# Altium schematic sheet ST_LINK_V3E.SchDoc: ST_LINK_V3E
size A3; Date: Not used; ApprovedBy: Not used; CheckedBy: Not used; Author: Not used; CompanyName: STMicroelectronics; DrawnBy: Not used; Engineer: Not used; Organization: Not used; Address1: Not used; Address2: Not used; Address3: Not used; Address4: Not used; DocumentNumber: Not used; Revision: Not used; SheetNumber: 15; SheetTotal: 16
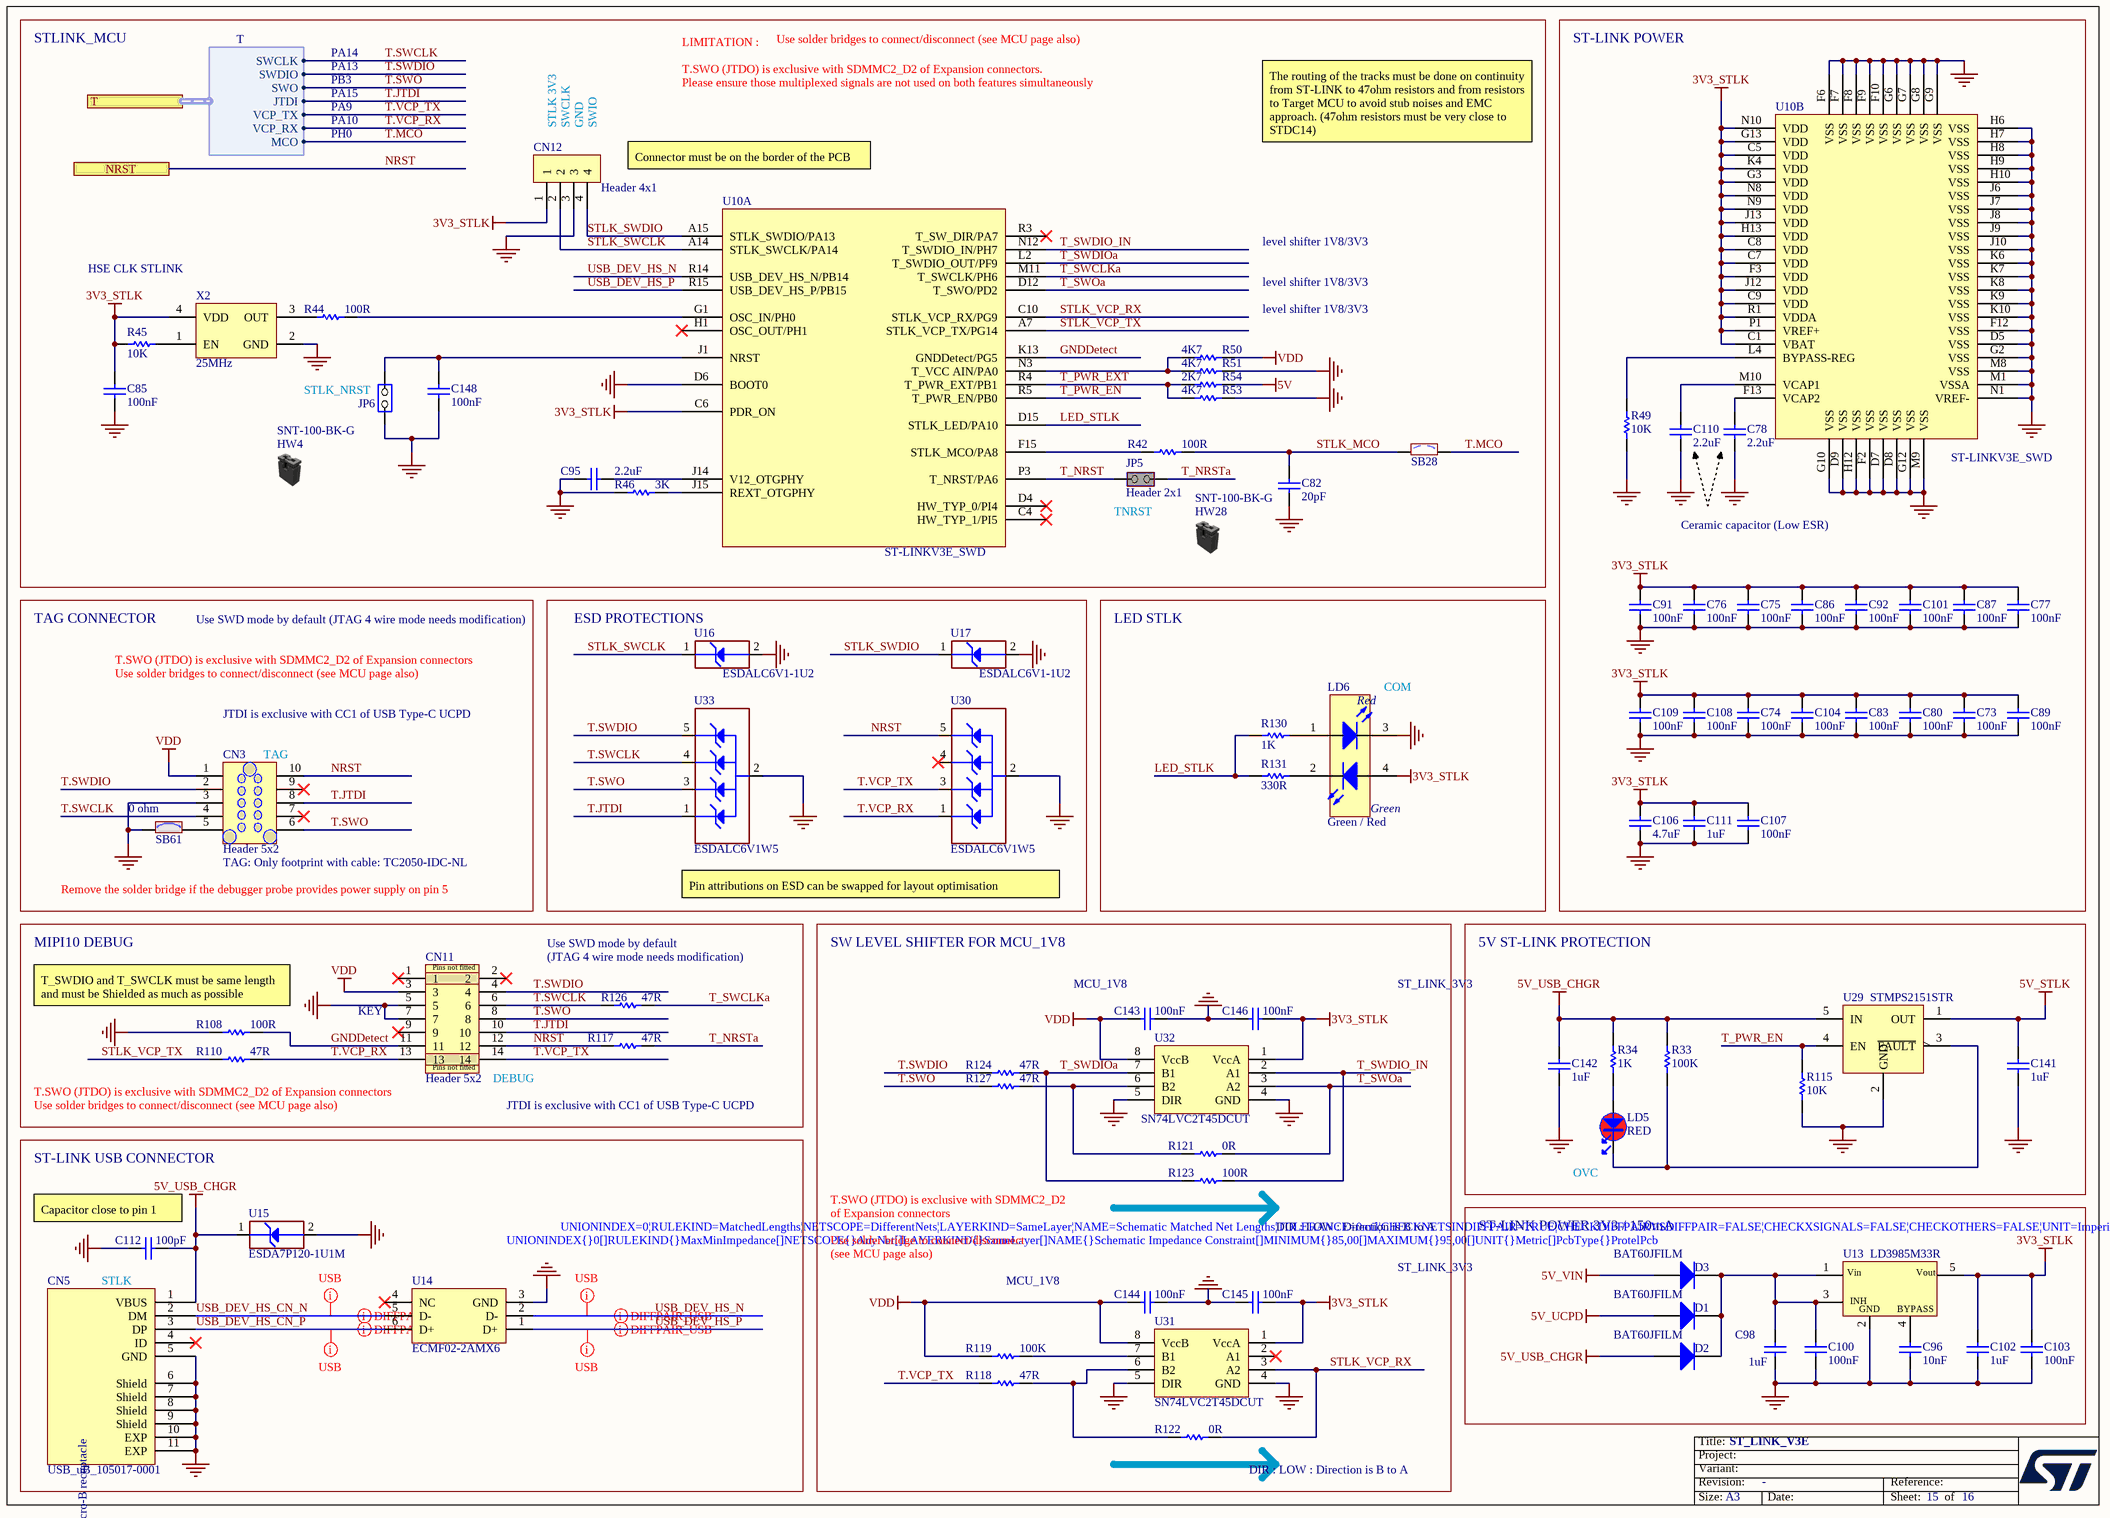
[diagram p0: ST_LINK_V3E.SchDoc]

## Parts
C73  value 100nF  [C0402]  (hidden comment: Capacitor)
C74  value 100nF  [C0402]  (hidden comment: Capacitor)
C75  value 100nF  [C0402]  (hidden comment: Capacitor)
C76  value 100nF  [C0402]  (hidden comment: Capacitor)
C77  value 100nF  [C0402]  (hidden comment: Capacitor)
C78  value 2.2uF  [C0603]  (hidden comment: Capacitor)
C80  value 100nF  [C0402]  (hidden comment: Capacitor)
C82  value 20pF  [C0402]  (hidden comment: Capacitor)
C83  value 100nF  [C0402]  (hidden comment: Capacitor)
C85  value 100nF  [C0402]  (hidden comment: Capacitor)
C86  value 100nF  [C0402]  (hidden comment: Capacitor)
C87  value 100nF  [C0402]  (hidden comment: Capacitor)
C89  value 100nF  [C0402]  (hidden comment: Capacitor)
C91  value 100nF  [C0402]  (hidden comment: Capacitor)
C92  value 100nF  [C0402]  (hidden comment: Capacitor)
C95  value 2.2uF  [C0603]  (hidden comment: Capacitor)
C96  value 10nF  [C0402]  (hidden comment: Capacitor)
C98  value 1uF  [C0402]  (hidden comment: Capacitor)
C100  value 100nF  [C0402]  (hidden comment: Capacitor)
C101  value 100nF  [C0402]  (hidden comment: Capacitor)
C102  value 1uF  [C0402]  (hidden comment: Capacitor)
C103  value 100nF  [C0402]  (hidden comment: Capacitor)
C104  value 100nF  [C0402]  (hidden comment: Capacitor)
C106  value 4.7uF  [C0603]  (hidden comment: Capacitor)
C107  value 100nF  [C0402]  (hidden comment: Capacitor)
C108  value 100nF  [C0402]  (hidden comment: Capacitor)
C109  value 100nF  [C0402]  (hidden comment: Capacitor)
C110  value 2.2uF  [C0603]  (hidden comment: Capacitor)
C111  value 1uF  [C0402]  (hidden comment: Capacitor)
C112  value 100pF  [C0402]  (hidden comment: Capacitor)
C141  value 1uF  [C0402]  (hidden comment: Capacitor)
C142  value 1uF  [C0402]  (hidden comment: Capacitor)
C143  value 100nF  [C0402]  (hidden comment: Capacitor)
C144  value 100nF  [C0402]  (hidden comment: Capacitor)
C145  value 100nF  [C0402]  (hidden comment: Capacitor)
C146  value 100nF  [C0402]  (hidden comment: Capacitor)
C148  value 100nF  [C0402]  (hidden comment: Capacitor)
CN3  value Header 5x2  [CON_TAG-C_TC2050-IDC-NL]  (hidden comment: Tag-10-C)
CN5  value USB_uB_105017-0001  [CON_USBMICROB_MOLEX_105017-0001_H2P90]  (hidden comment: USB_uB_105017.0001)
CN11  value Header 5x2  [CON_STDC14_Receiver_MEDIUM__3D_FTSH-105-01-L-DV-K]  (hidden comment: Header 7x2_MIPI10_on_STDC14)
CN12  Header 4x1  [CON_SAMTEC_TSW-104-07-G-S]
D1  BAT60JFILM  [DIO_SOD323]
D2  BAT60JFILM  [DIO_SOD323]
D3  BAT60JFILM  [DIO_SOD323]
HW4  value SNT-100-BK-G  (hidden comment: Shunt Black 2.54mm)  (mechanical)
HW28  value SNT-100-BK-G  (hidden comment: Shunt Black 2.54mm)  (mechanical)
JP5  value Header 2x1  [CON_SAMTEC_TSW-102-07-G-S]  (hidden comment: Jumper_Header 2x1 Fitted)
JP6  Jumper_Header 2x1  [CON_SAMTEC_TSW-102-07-G-S]  (value not drawn)
LD5  value RED  [LED_0603_OSRAM_LS-Q976-NR-1_RED_1A2K_H0P8]  (hidden comment: LED_red)
LD6  value Green / Red  [LED_BI-GR_WE-150141SV73110]  (hidden comment: LED_BICOLOR)
R33  value 100K  [R0402]  (hidden comment: Resistor)
R34  value 1K  [R0402]  (hidden comment: Resistor)
R42  value 100R  [R0402]  (hidden comment: Resistor)
R44  value 100R  [R0402]  (hidden comment: Resistor)
R45  value 10K  [R0402]  (hidden comment: Resistor)
R46  value 3K  [R0402]  (hidden comment: Resistor)
R49  value 10K  [R0402]  (hidden comment: Resistor)
R50  value 4K7  [R0402]  (hidden comment: Resistor)
R51  value 4K7  [R0402]  (hidden comment: Resistor)
R53  value 4K7  [R0402]  (hidden comment: Resistor)
R54  value 2K7  [R0402]  (hidden comment: Resistor)
R108  value 100R  [R0402]  (hidden comment: Resistor)
R110  value 47R  [R0402]  (hidden comment: Resistor)
R115  value 10K  [R0402]  (hidden comment: Resistor)
R117  value 47R  [R0402]  (hidden comment: Resistor)
R118  value 47R  [R0402]  (hidden comment: Resistor)
R119  value 100K  [R0402]  (hidden comment: Resistor)
R121  value 0R  [R0402]  (hidden comment: Resistor)
R122  value 0R  [R0402]  (hidden comment: Resistor)
R123  value 100R  [R0402]  (hidden comment: Resistor)
R124  value 47R  [R0402]  (hidden comment: Resistor)
R126  value 47R  [R0402]  (hidden comment: Resistor)
R127  value 47R  [R0402]  (hidden comment: Resistor)
R130  value 1K  [R0402]  (hidden comment: Resistor)
R131  value 330R  [R0402]  (hidden comment: Resistor)
SB28  SB_OFF  [SOLDER-BRIDGE_R0402-0R]  (value not drawn)
SB61  value 0 ohm  [SOLDER-BRIDGE_R0402-0R]  (hidden comment: SB_ON)
U10  ST-LINKV3E_SWD  [ICC_UFBGA201_176+25_10X10_P065]  (parts A,B of 2)
U13  LD3985M33R  [REG_SOT23-5L]
U14  ECMF02-2AMX6  [ESD_QFN-6L_1P7X1P5_P050]
U15  value ESDA7P120-1U1M  [ESD_QFN1610_2N_1K_2A]  (hidden comment: ESD-TRANSIL)
U16  value ESDALC6V1-1U2  [ESD_ST0201]  (hidden comment: ESD-TRANSIL)
U17  value ESDALC6V1-1U2  [ESD_ST0201]  (hidden comment: ESD-TRANSIL)
U29  STMPS2151STR  [MOS_SOT23-5L]
U30  ESDALC6V1W5  [ESD_SOT323-5L]
U31  SN74LVC2T45DCUT  [ICC_VSSOP8_DCU_R-PDSO-G8_2X2P30_P050]
U32  SN74LVC2T45DCUT  [ICC_VSSOP8_DCU_R-PDSO-G8_2X2P30_P050]
U33  ESDALC6V1W5  [ESD_SOT323-5L]
X2  value 25MHz  [OSC_NDK_NZ2520SB_4P]  (hidden comment: OSCILLATOR_4_PINS)

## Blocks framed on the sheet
STLINK_MCU: C82 C85 C95 C148 CN12 HW4 HW28 JP5 JP6 R42 R44-R46 R50 R51 R53 R54 SB28 U10 X2
ST-LINK POWER: C73-C78 C80 C83 C86 C87 C89 C91 C92 C101 C104 C106-C111 R49 U10
TAG CONNECTOR: CN3 SB61
ESD PROTECTIONS: U16 U17 U30 U33
LED STLK: LD6 R130 R131
MIPI10 DEBUG: CN11 R108 R110 R117 R126
SW LEVEL SHIFTER FOR MCU_1V8: C143-C146 R118 R119 R121-R124 R127 U31 U32
5V ST-LINK PROTECTION: C141 C142 LD5 R33 R34 R115 U29
ST-LINK USB CONNECTOR: C112 CN5 U14 U15
ST-LINK POWER 3V3 / 150mA: C96 C98 C100 C102 C103 D1-D3 U13

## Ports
NRST, T (harness T)

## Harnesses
T: SWCLK, SWDIO, SWO, JTDI, VCP_RX, VCP_TX, MCO

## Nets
3V3_STLK: C73.1 C74.1 C75.1 C76.1 C77.1 C80.1 C83.1 C85.1 C86.1 C87.1 C89.1 C91.1 C92.1 C101.1 C102.2 C103.2 C104.1 C106.2 C107.1 C108.1 C109.1 C111.2 C145.2 C146.2 CN12.1 LD6.4(Green_anode) R45.1 U10.C1(VBAT) U10.C5(VDD) U10.C6(PDR_ON) U10.C7(VDD) U10.C8(VDD) U10.C9(VDD) U10.F3(VDD) U10.G3(VDD) U10.G13(VDD) U10.H13(VDD) U10.J12(VDD) U10.J13(VDD) U10.K4(VDD) U10.N8(VDD) U10.N9(VDD) U10.N10(VDD) U10.P1(VREF+) U10.R1(VDDA) U13.5(Vout) U31.1(VccA) U32.1(VccA) X2.4(VDD)
5V: R54.1
5V_STLK: C141.2 U29.1(OUT)
5V_UCPD: D1.1(A)
5V_USB_CHGR: C112.2 C142.2 CN5.1(VBUS) D2.1(A) R33.2 R34.2 U15.1(IO1) U29.5(IN)
5V_VIN: D3.1(A)
GND: C73.2 C74.2 C75.2 C76.2 C77.2 C78.1 C80.2 C82.1 C83.2 C85.2 C86.2 C87.2 C89.2 C91.2 C92.2 C95.1 C96.1 C98.1 C100.1 C101.2 C102.1 C103.1 C104.2 C106.1 C107.2 C108.2 C109.2 C110.1 C111.1 C112.1 C141.1 C142.1 C143.2 C144.2 C145.1 C146.1 C148.2 CN3.3 CN5.5(GND) CN5.6(Shield) CN5.7(Shield) CN5.8(Shield) CN5.9(Shield) CN5.10(EXP) CN5.11(EXP) CN11.5 CN11.7 CN12.3 JP6.1(COMMON) LD6.3(RED_cathode) R46.1 R49.1 R51.2 R53.1 R108.1 R115.1 SB61.1 U10.D5(VSS) U10.D6(BOOT0) U10.D7(VSS) U10.D8(VSS) U10.D9(VSS) U10.F2(VSS) U10.F6(VSS) U10.F7(VSS) U10.F8(VSS) U10.F9(VSS) U10.F10(VSS) U10.F12(VSS) U10.G2(VSS) U10.G6(VSS) U10.G7(VSS) U10.G8(VSS) U10.G9(VSS) U10.G10(VSS) U10.G12(VSS) U10.H6(VSS) U10.H7(VSS) U10.H8(VSS) U10.H9(VSS) U10.H10(VSS) U10.H12(VSS) U10.J6(VSS) U10.J7(VSS) U10.J8(VSS) U10.J9(VSS) U10.J10(VSS) U10.K6(VSS) U10.K7(VSS) U10.K8(VSS) U10.K9(VSS) U10.K10(VSS) U10.M1(VSSA) U10.M8(VSS) U10.M9(VSS) U10.N1(VREF-) U13.2(GND) U14.3(GND) U15.2(GND) U16.2(GND) U17.2(GND) U29.2(GND) U30.2(GND) U31.4(GND) U31.5(DIR) U32.4(GND) U32.5(DIR) U33.2(GND) X2.2(GND)
VDD: C143.1 C144.1 CN3.1 CN11.3 R50.2 R119.1 U31.8(VccB) U32.8(VccB)
GNDDetect: CN11.11 R108.2 U10.K13(GNDDetect/PG5)
LED_STLK: R130.2 R131.2 U10.D15(STLK_LED/PA10)
NRST: CN3.10 CN11.12 R117.1 U30.5(IO4) ; port NRST
STLK_MCO: C82.2 R42.2 SB28.1
STLK_SWCLK: CN12.2 U10.A14(STLK_SWCLK/PA14) U16.1(IO1)
STLK_SWDIO: CN12.4 U10.A15(STLK_SWDIO/PA13) U17.1(IO1)
STLK_VCP_RX: R122.2 U10.C10(STLK_VCP_RX/PG9) U31.3(A2)
STLK_VCP_TX: R110.1 U10.A7(STLK_VCP_TX/PG14)
T.JTDI: CN3.8 CN11.10 U33.1(IO1) ; port T.JTDI
T.MCO: SB28.2 ; port T.MCO
T.SWCLK: CN3.4 CN11.6 R126.1 U33.4(IO3) ; port T.SWCLK
T.SWDIO: CN3.2 CN11.4 R124.1 U33.5(IO4) ; port T.SWDIO
T.SWO: CN3.6 CN11.8 R127.1 U33.3(IO2) ; port T.SWO
T.VCP_RX: CN11.13 R110.2 U30.1(IO1) ; port T.VCP_RX
T.VCP_TX: CN11.14 R118.1 U30.3(IO2) ; port T.VCP_TX
T_NRST: JP5.1(COMMON) U10.P3(T_NRST/PA6)
T_NRSTa: JP5.2(NO) R117.2
T_PWR_EN: R115.2 U10.R5(T_PWR_EN/PB0) U29.4(EN)
T_PWR_EXT: R53.2 R54.2 U10.R4(T_PWR_EXT/PB1)
T_SWCLKa: R126.2 U10.M11(T_SWCLK/PH6)
T_SWDIO_IN: R123.2 U10.N12(T_SWDIO_IN/PH7) U32.2(A1)
T_SWDIOa: R123.1 R124.2 U10.L2(T_SWDIO_OUT/PF9) U32.7(B1)
T_SWOa: R121.2 U10.D12(T_SWO/PD2) U32.3(A2)
USB_DEV_HS_CN_N: CN5.2(DM) U14.5(D-)
USB_DEV_HS_CN_P: CN5.3(DP) U14.6(D+)
USB_DEV_HS_N: U10.R14(USB_DEV_HS_N/PB14) U14.2(D-)
USB_DEV_HS_P: U10.R15(USB_DEV_HS_P/PB15) U14.1(D+)
NetC78_2: C78.2 U10.F13(VCAP2)
NetC95_2: C95.2 U10.J14(V12_OTGPHY)
NetC96_2: C96.2 U13.4(BYPASS)
NetC98_2: C98.2 C100.2 D1.2(K) D2.2(K) D3.2(K) U13.1(Vin) U13.3(CE)
NetC110_2: C110.2 U10.M10(VCAP1)
NetC148_1: C148.1 JP6.2(NO) U10.J1(NRST)
NetCN3_5: CN3.5 SB61.2
NetLD5_1: LD5.1 R34.1
NetLD5_2: LD5.2 R33.1 U29.3(~{FAULT})
NetLD6_1: LD6.1(Red_anode) R130.1
NetLD6_2: LD6.2(Green_cathode) R131.1
NetR42_1: R42.1 U10.F15(STLK_MCO/PA8)
NetR44_1: R44.1 X2.3(OUT)
NetR44_2: R44.2 U10.G1(OSC_IN/PH0)
NetR45_2: R45.2 X2.1(EN)
NetR46_2: R46.2 U10.J15(REXT_OTGPHY)
NetR49_2: R49.2 U10.L4(BYPASS-REG)
NetR50_1: R50.1 R51.1 U10.N3(T_VCC_AIN/PA0)
NetR118_2: R118.2 R122.1 U31.6(B2)
NetR119_2: R119.2 U31.7(B1)
NetR121_1: R121.1 R127.2 U32.6(B2)

Not connected (* = marked no-connect by the designer): CN3 7* 9*; CN5 4(ID)*; CN11 1* 2* 9*; U10 C4(HW_TYP_1/PI5)* D4(HW_TYP_0/PI4)* H1(OSC_OUT/PH1)* R3(T_SW_DIR/PA7)*; U14 4(NC)*; U30 4(IO3)*; U31 2(A1)*

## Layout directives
differential pair; rule Impedance Constraint [Min = 85.00    Max = 95.00    ]: USB_DEV_HS_CN_N, USB_DEV_HS_CN_P, USB_DEV_HS_N, USB_DEV_HS_P
rule Undefined; rule Matched Net Lengths [Tolerance = 0mil]; rule Impedance Constraint [Min = 85.00    Max = 95.00    ]: USB_DEV_HS_CN_N, USB_DEV_HS_CN_P, USB_DEV_HS_N, USB_DEV_HS_P

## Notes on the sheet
- Use solder bridges to connect/disconnect (see MCU page also)
- PA14
- PA13
- PB3
- PA15
- PA9
- LIMITATION :
  T.SWO (JTDO) is exclusive with SDMMC2_D2 of Expansion connectors.
  Please ensure those multiplexed signals are not used on both features simultaneously
- PA10
- PH0
- STLK 3V3
- SWCLK
- GND
- SWIO
- Connector must be on the border of the PCB
- The routing of the tracks must be done on continuity from ST-LINK to 47ohm resistors and from resistors to Target MCU to avoid stub noises and EMC approach. (47ohm resistors must be very close to STDC14)
- level shifter 1V8/3V3
- HSE CLK STLINK
- (near JP6) STLK_NRST
- (near JP5) TNRST
- Ceramic capacitor (Low ESR)
- Use SWD mode by default (JTAG 4 wire mode needs modification)
- T.SWO (JTDO) is exclusive with SDMMC2_D2 of Expansion connectors
- JTDI is exclusive with CC1 of USB Type-C UCPD
- (near LD6) COM
- (near CN3) TAG
- Remove the solder bridge if the debugger probe provides power supply on pin 5
- (near CN3) TAG: Only footprint with cable: TC2050-IDC-NL
- Pin attributions on ESD can be swapped for layout optimisation
- Use SWD mode by default
- (near R126) (JTAG 4 wire mode needs modification)
- MCU_1V8
- ST_LINK_3V3
- (near R108) T_SWDIO and T_SWCLK must be same length and must be Shielded as much as possible
- (near CN11) KEY
- (near CN11) DEBUG
- (near LD5) OVC
- (near C112) Capacitor close to pin 1
- T.SWO (JTDO) is exclusive with SDMMC2_D2
- of Expansion connectors
- Use solder bridge to connect/disconnect
- (see MCU page also)
- (near R123) DIR : LOW : Direction is B to A
- STLK
- (near R122) DIR : LOW : Direction is B to A

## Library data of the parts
C73-C77 C80 C83 C85-C87 C89 C91 C92 C100 C101 C103 C104 C107-C109 C143-C146 C148 = MCD-00006: Capacitor, MLCC, 100nF, 16V, X7R, +/-10%, 0402, T=0.5mm; Manufacturer_Part_Number: CC0402KRX7R7BB104; Manufacturer: YAGEO; Part_Preference: Recommended; Order_Code_RS: 616-9701; Component_Country_Of_Origin: China
C78 C95 C110 = MCD-00012: Capacitor, MLCC, 2.2uF, 10V, X5R, +/- 10%, 0603, T=0.8mm; Manufacturer_Part_Number: CC0603KRX5R6BB225; Manufacturer: YAGEO; BMS_Part_Number: 9142010; Part_Preference: Recommended; Component_Country_Of_Origin: China
C82 = MCD-00016: Capacitor, MLCC, 20pF, 50V, NPO, +/- 5%, 0402, T=0.5mm; Manufacturer_Part_Number: CC0402JRNPO9BN200; Manufacturer: YAGEO; Part_Preference: Recommended; Component_Country_Of_Origin: China
C96 = MCD-00011: Capacitor, MLCC, 10nF, 16V, X7R, +/-10%, 0402, T=0.5mm; Manufacturer_Part_Number: CC0402KRX7R7BB103; Manufacturer: YAGEO; Part_Preference: Recommended; Order_Code_RS: 669-8688; Component_Country_Of_Origin: China
C98 C102 C111 C141 C142 = MCD-02609: Capacitor, MLCC, 1uF, 25V, X5R, +/-10%, 0402, T=0.5mm; Part_Preference: Recommended; Manufacturer: YAGEO; Manufacturer_Part_Number: CC0402KRX5R8BB105
C106 = MCD-00009: Capacitor, MLCC, 4.7uF, 16V, X5R, +/-10%, 0603, T=0.8mm; Manufacturer_Part_Number: CC0603KRX5R7BB475; Manufacturer: YAGEO; Part_Preference: Recommended; Component_Country_Of_Origin: China
C112 = MCD-00205: Capacitor, MLCC, 100pF, 50V, NPO, +/-5%, 0402, T=0.5mm; Manufacturer_Part_Number: CC0402JRNPO9BN101; Manufacturer: YAGEO; Part_Preference: Recommended; Component_Country_Of_Origin: China
CN3 = MCD-00031: Header_Plug-of-nails, 5x2, 1.27mm, No legs; Part_Type: Connector; Manufacturer_Part_Number: TC2050-IDC-NL-FP; Manufacturer: TAG-CONNECTLLC; Part_Preference: Recommended
CN5 = MCD-00028: MicroUSB_TypeB, 5pins, 0.65mm, RA, SMD, T=2.9mm; Manufacturer_Part_Number: 1050170001; Manufacturer: MOLEX; Part_Type: Connector; Part_Preference: Recommended; Order_Code_RS: 848-6764; Component_Country_Of_Origin: Unknown
CN11 = MCD-02021: Header_MIPI10, 5x2, 1.27mm, VR, SMD, T=6.1mm; Part_Type: Connector; Manufacturer: SAMTEC; Manufacturer_Part_Number: FTSH-105-01-L-DV-K-P-TR; Part_Preference: Recommended; Component_Country_Of_Origin: China, Costa Rica, Malaysia, United States, Vietnam
CN12 = MCD-00029: Header, 4x1, 2.54mm, VR, TH, T=5.84mm/2.54mm; Manufacturer_Part_Number: TSW-104-07-G-S; Manufacturer: SAMTEC; Part_Type: Connector; Part_Preference: Recommended; Order_Code_RS: 161-2261; Component_Country_Of_Origin: China, Costa Rica, Malaysia, United States, Vietnam
D1-D3 = MCD-00034: Manufacturer: STMICROELECTRONICS; Part_Type: Diode; BMS_Part_Number: 9151097; Part_Preference: Recommended; Manufacturer_HQ_COO: EU; Component_Country_Of_Origin: China
HW4 HW28 = MCD-00043: SHUNT 2.54mm BLACK; Manufacturer: SAMTEC; Part_Type: Misc; Part_Preference: Recommended; Component_Country_Of_Origin: China, Costa Rica, Malaysia, United States, Vietnam
JP5 = MCD-01904: Header, 2x1, 2.54mm, VR, TH, T=5.84mm/2.54mm; Part_Preference: Recommended; Part_Type: Connector; Manufacturer: SAMTEC; Manufacturer_Part_Number: TSW-102-07-G-S; Order_Code_RS: 155-7981; Component_Country_Of_Origin: China, Costa Rica, Malaysia, United States, Vietnam
JP6 = MCD-00045: Header, 2x1, 2.54mm, VR, TH, T=5.84mm/2.54mm; Part_Type: Connector; Manufacturer_Part_Number: TSW-102-07-G-S; Manufacturer: SAMTEC; Part_Preference: Recommended; Order_Code_RS: 155-5312; Component_Country_Of_Origin: China, Costa Rica, Malaysia, United States, Vietnam
LD5 = MCD-00586: LED Red, 0603 SMD, Forward Voltage Typ=2V, Max=2.5V; Manufacturer_Part_Number: LS Q976-NR-1; Manufacturer: OSRAM OPTO SEMICONDUCTORS; Part_Type: Display; Part_Preference: Recommended; Component_Country_Of_Origin: Unknown; ShowFields: YES; ID: 3158
LD6 = MCD-02631: LED Bicolor, Green/Red, 2V, 20mA,  4-PLCC; Part_Type: Display; Part_Preference: Recommended; Manufacturer: WURTH ELEKTRONIK; Manufacturer_Part_Number: 150141SV73110; Order_Code_RS: 184-6963; Component_Country_Of_Origin: China; ShowFields: YES; ID: 4737
R33 R119 = MCD-00059: Resistor, 100K, 0402, +/-1%, 1/16W; Manufacturer_Part_Number: RC0402FR-07100KL; Manufacturer: YAGEO; Part_Preference: Recommended; Component_Country_Of_Origin: China
R34 R130 = MCD-00061: Resistor, 1K, 0402, +/-1%,1/16W; Manufacturer_Part_Number: RC0402FR-071KL; Manufacturer: YAGEO; Part_Preference: Recommended; Component_Country_Of_Origin: China; ShowFields: YES; ID: 2532
R42 R44 R108 R123 = MCD-00067: Resistor, 100R, 0402, +/- 1%, 1/16W; Manufacturer_Part_Number: RC0402FR-07100RL; Manufacturer: YAGEO; Part_Preference: Recommended; Component_Country_Of_Origin: China
R45 R49 R115 = MCD-00053: Resistor, 10K, 0402, +/-1%, 1/16W; Manufacturer_Part_Number: RC0402FR-0710KL; Manufacturer: YAGEO; BMS_Part_Number: 9131590; Part_Preference: Recommended; Component_Country_Of_Origin: China
R46 = MCD-00185: Resistor, 3K, 0402, +/-1%, 1/16W; Manufacturer_Part_Number: RC0402FR-073KL; Manufacturer: YAGEO; Part_Preference: Recommended; Component_Country_Of_Origin: China
R50 R51 R53 = MCD-00065: Resistor, 4K7, 0402, +/-1%, 1/16W; Manufacturer_Part_Number: RC0402FR-074K7L; Manufacturer: YAGEO; Part_Preference: Recommended; Component_Country_Of_Origin: China
R54 = MCD-00055: Resistor, 2K7, 0402, +/-1%, 1/16W; Manufacturer_Part_Number: RC0402FR-072K7L; Manufacturer: YAGEO; Part_Preference: Recommended; Component_Country_Of_Origin: China
R110 R117 R118 R124 R126 R127 = MCD-00481: Resistor, 47R, 0402, +/-1%, 1/16W; Manufacturer_Part_Number: RC0402FR-0747RL; Manufacturer: YAGEO; Part_Preference: Recommended; Component_Country_Of_Origin: China
R121 R122 = MCD-00052: Resistor, 0R, 0402, +/-5%, 1/16W; Manufacturer_Part_Number: RC0402JR-070RL; Manufacturer: YAGEO; Part_Preference: Recommended; Order_Code_RS: 618-5804; Component_Country_Of_Origin: China
R131 = MCD-00062: Resistor, 330R, 0402, +/-1%, 1/16W; Manufacturer_Part_Number: RC0402FR-07330RL; Manufacturer: YAGEO; Part_Preference: Recommended; Component_Country_Of_Origin: China
SB28 = MCD-02162: Solder Bridge 0402 OFF; Part_Type: Misc; Manufacturer_Part_Number: RC0402JR-070RL; Manufacturer: YAGEO; Part_Preference: Recommended; Order_Code_RS: 618-5804; Component_Country_Of_Origin: China
SB61 = MCD-01618: Solder Bridge 0402 ON; Part_Type: Misc; Part_Preference: Recommended; Manufacturer: YAGEO; Manufacturer_Part_Number: RC0402JR-070RL; Order_Code_RS: 618-5804; Component_Country_Of_Origin: China; ShowFields: YES; ID: 3718
U10 = MCD-00596: STM32F723IEK  (STM32F7) BGA176; Part_Type: IC; Manufacturer_Part_Number: STM32F723IEK6; Manufacturer: STMICROELECTRONICS; BMS_Part_Number: 9175300; Part_Preference: Recommended; Manufacturer_HQ_COO: EU; Component_Country_Of_Origin: Philippines
U13 = MCD-00086: Ultra low drop-low noise BiCMOS voltage, regulators low ESR capacitors compatible; Manufacturer: STMICROELECTRONICS; Part_Type: IC; BMS_Part_Number: 9176161; Part_Preference: Recommended; Manufacturer_HQ_COO: EU; Component_Country_Of_Origin: China
U14 = MCD-00649: Common mode filter with ESD protection for USB 2.0 interface; Part_Type: Diode; Manufacturer: STMICROELECTRONICS; BMS_Part_Number: 9151138; Part_Preference: Recommended; Manufacturer_HQ_COO: EU; Component_Country_Of_Origin: China
U15 = MCD-01026: High power transient voltage suppressor; Part_Type: Diode; Manufacturer: STMICROELECTRONICS; BMS_Part_Number: 9179046; Part_Preference: Recommended; Manufacturer_HQ_COO: EU; Component_Country_Of_Origin: China
U16 U17 = MCD-00170: ESD protection 6V1; Part_Type: Diode; Manufacturer: STMICROELECTRONICS; BMS_Part_Number: 9151132; Part_Preference: Recommended; Manufacturer_HQ_COO: EU; Component_Country_Of_Origin: China
U29 = MCD-00159: 500mA, Enhanced single channel power switches with active high enable pin; Part_Type: IC; Manufacturer: STMICROELECTRONICS; BMS_Part_Number: 9159009; Part_Preference: Recommended; Manufacturer_HQ_COO: EU; Component_Country_Of_Origin: Malaysia
U30 U33 = MCD-00136: Dual Transil array for ESD protection; Part_Type: Diode; Manufacturer: STMICROELECTRONICS; BMS_Part_Number: 9151112; Part_Preference: Recommended; Manufacturer_HQ_COO: EU; Component_Country_Of_Origin: China
U31 U32 = MCD-00264: Dual bit dual supply bus transceiver; Part_Type: IC; Manufacturer: TEXAS INSTRUMENTS; BMS_Part_Number: 9169311; Part_Preference: Recommended; Component_Country_Of_Origin: Thailand
X2 = MCD-00597: Oscillator, SPXO, 25Mhz, +/-50ppm, 3V3, square wave, 2.5x2mm; Part_Type: Crystal_Osc; Manufacturer_Part_Number: NZ2520SH-25MHZ-END4869C; Manufacturer: NDK; BMS_Part_Number: 9157050; Part_Preference: Recommended; Component_Country_Of_Origin: Unknown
